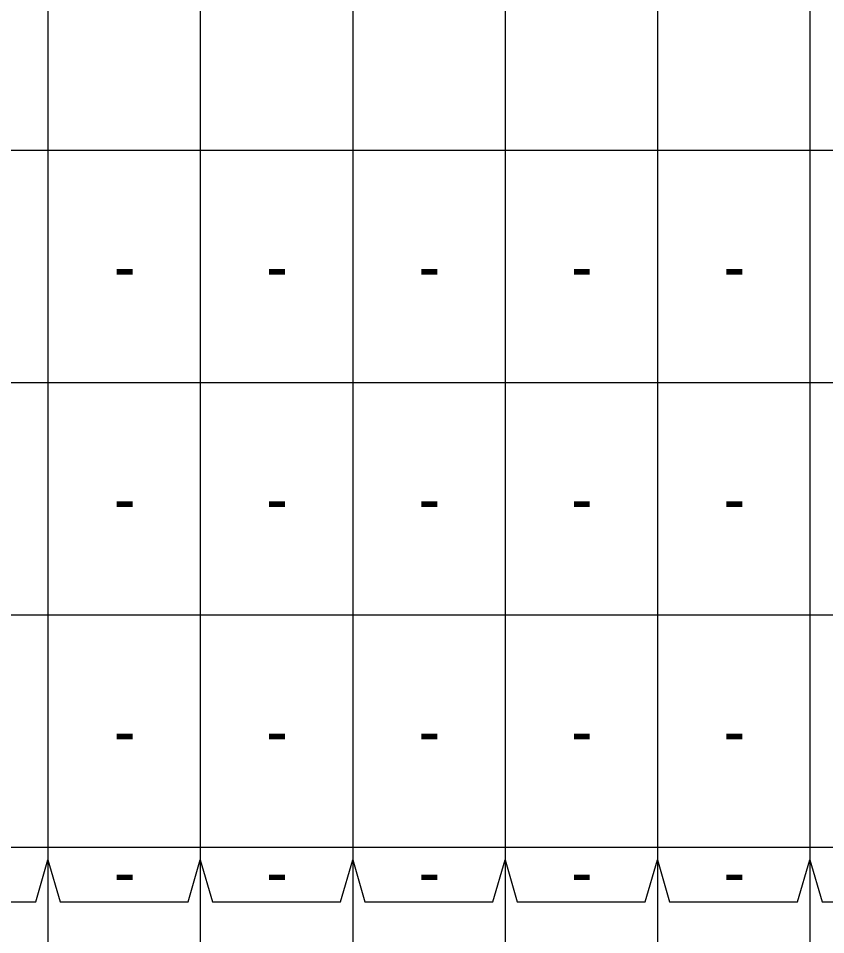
# Model space of a CAD drawing. Extents: x 0 to 0.833, y -0.323 to 0.608.
# Drawn here: x 0.6168 to 0.7272, y 0.0833 to 0.2085 of the extents above; entities that cross this region are included whole.
import ezdxf

# ---------------------------------------------------------------- set-up
doc = ezdxf.new("R2010")
doc.units = 0

msp = doc.modelspace()

# ---------------------------------------------------------------- linework, layer by layer
for points in [[(0.6625, 0.55417), (0.6625, -0.28575)], [(0.725, 0.55417), (0.725, -0.28575)], [(0.62083, 0.54167), (0.62083, -0.28575)], [(0.64167, 0.54167), (0.64167, -0.28575)], [(0.68333, 0.54167), (0.68333, -0.28575)], [(0.70417, 0.54167), (0.70417, -0.28575)], [(0.725, 0.54167), (0.725, -0.28575)], [(0.6, 0.1905), (0.62083, 0.1905)], [(0.62083, 0.1905), (0.64167, 0.1905)], [(0.64167, 0.1905), (0.6625, 0.1905)], [(0.6625, 0.1905), (0.68333, 0.1905)], [(0.68333, 0.1905), (0.70417, 0.1905)], [(0.70417, 0.1905), (0.725, 0.1905)], [(0.725, 0.1905), (0.75, 0.1905)], [(0.6, 0.15875), (0.62083, 0.15875)], [(0.62083, 0.15875), (0.64167, 0.15875)], [(0.64167, 0.15875), (0.6625, 0.15875)], [(0.6625, 0.15875), (0.68333, 0.15875)], [(0.68333, 0.15875), (0.70417, 0.15875)], [(0.70417, 0.15875), (0.725, 0.15875)], [(0.725, 0.15875), (0.75, 0.15875)], [(0.6, 0.127), (0.62083, 0.127)], [(0.62083, 0.127), (0.64167, 0.127)], [(0.64167, 0.127), (0.6625, 0.127)], [(0.6625, 0.127), (0.68333, 0.127)], [(0.68333, 0.127), (0.70417, 0.127)], [(0.70417, 0.127), (0.725, 0.127)], [(0.725, 0.127), (0.75, 0.127)], [(0.6, 0.09525), (0.62083, 0.09525)], [(0.62083, 0.09525), (0.64167, 0.09525)], [(0.64167, 0.09525), (0.6625, 0.09525)], [(0.6625, 0.09525), (0.68333, 0.09525)], [(0.68333, 0.09525), (0.70417, 0.09525)], [(0.70417, 0.09525), (0.725, 0.09525)], [(0.725, 0.09525), (0.75, 0.09525)], [(0.6, 0.09349), (0.60167, 0.08775), (0.61917, 0.08775), (0.62083, 0.09349)], [(0.62083, 0.09349), (0.6225, 0.08775), (0.64, 0.08775), (0.64167, 0.09349)], [(0.64167, 0.09349), (0.64333, 0.08775), (0.66083, 0.08775), (0.6625, 0.09349)], [(0.6625, 0.09349), (0.66417, 0.08775), (0.68167, 0.08775), (0.68333, 0.09349)], [(0.68333, 0.09349), (0.685, 0.08775), (0.7025, 0.08775), (0.70417, 0.09349)], [(0.70417, 0.09349), (0.70583, 0.08775), (0.72333, 0.08775), (0.725, 0.09349)], [(0.725, 0.09349), (0.72667, 0.08775), (0.74833, 0.08775), (0.75, 0.09349)]]:
    msp.add_lwpolyline(points)

# ---------------------------------------------------------------- texts
for p in [(0.62984, 0.17129), (0.65068, 0.17129), (0.67151, 0.17129), (0.69234, 0.17129), (0.71318, 0.17129), (0.62984, 0.13954), (0.65068, 0.13954), (0.67151, 0.13954), (0.69234, 0.13954), (0.71318, 0.13954), (0.62984, 0.10779), (0.65068, 0.10779), (0.67151, 0.10779), (0.69234, 0.10779), (0.71318, 0.10779), (0.62984, 0.08854), (0.65068, 0.08854), (0.67151, 0.08854), (0.69234, 0.08854), (0.71318, 0.08854)]:
    msp.add_text('-', height=0.00667).set_placement(p)

doc.saveas('drawing.dxf')
